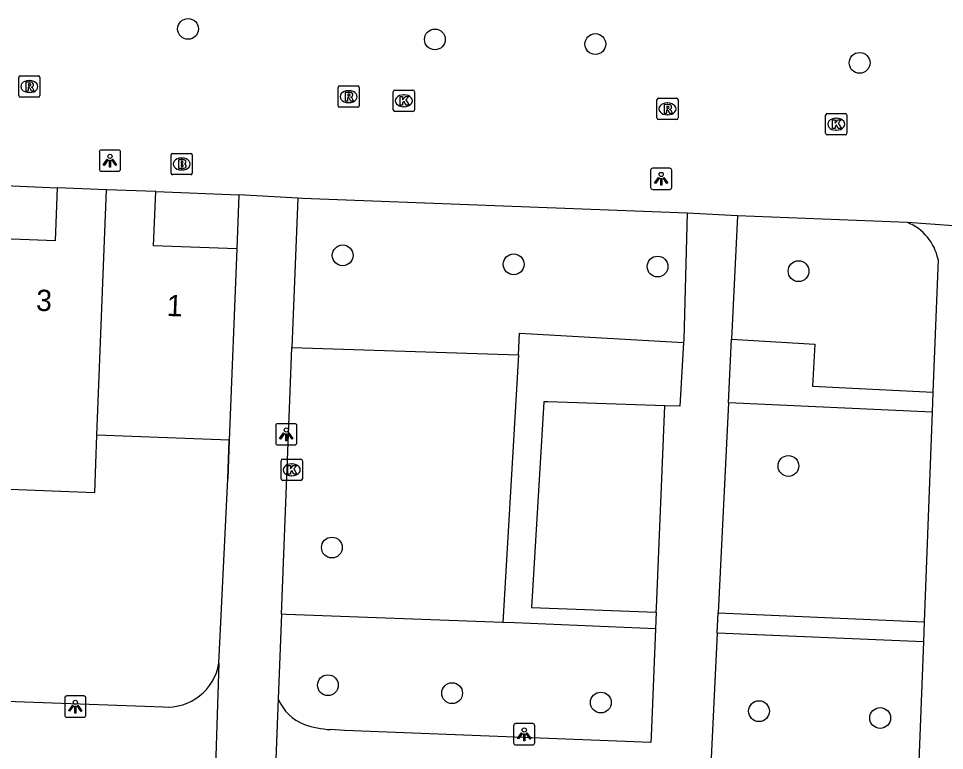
# Model space of a CAD drawing. Extents: x 160787 to 161428, y 386828 to 387483.
# Drawn here: x 161261.11 to 161304.65, y 387283.58 to 387318 of the extents above; entities that cross this region are included whole.
import ezdxf

# ---------------------------------------------------------------- set-up
doc = ezdxf.new("R2010")
doc.units = 0
for name, color, linetype in [('IMGEO_Boom', 7, 'Continuous'), ('IMGEO_Brandkraan', 7, 'Continuous'), ('IMGEO_Groenvoorziening', 7, 'Continuous'), ('IMGEO_Kolk', 7, 'Continuous'), ('IMGEO_Lichtpunt', 7, 'Continuous'), ('IMGEO_Muur', 7, 'Continuous'), ('IMGEO_Pand', 7, 'Continuous'), ('IMGEO_Pand_nummerreeks', 7, 'Continuous'), ('IMGEO_Rijbaan_lokaal_open', 7, 'Continuous'), ('IMGEO_Rioolput', 7, 'Continuous'), ('IMGEO_Voetpad_open', 7, 'Continuous')]:
    doc.layers.add(name, color=color, linetype=linetype)

msp = doc.modelspace()

# ---------------------------------------------------------------- linework, layer by layer
at = {"layer": 'IMGEO_Boom'}
for centre in [(161269.081, 387317.508), (161280.689, 387317.015), (161288.233, 387316.797), (161300.661, 387315.912), (161276.353, 387306.861), (161284.392, 387306.44), (161291.161, 387306.334), (161297.789, 387306.118), (161297.313, 387296.96), (161275.845, 387293.124), (161275.658, 387286.65), (161281.497, 387286.276), (161288.491, 387285.835), (161295.929, 387285.431), (161301.628, 387285.109)]:
    msp.add_circle(centre, 0.489, dxfattribs=at)
at = {"layer": 'IMGEO_Brandkraan'}
for p, q in [((161268.279, 387310.73), (161268.279, 387311.582)), ((161268.354, 387311.656), (161269.206, 387311.656)), ((161268.767, 387311.436), (161268.792, 387311.436)), ((161269.28, 387311.582), (161269.28, 387310.73)), ((161268.79, 387310.876), (161268.765, 387310.876)), ((161269.206, 387310.656), (161268.354, 387310.656))]:
    msp.add_line(p, q, dxfattribs=at)
for points in [[(161268.279, 387310.73), (161268.279, 387311.582)], [(161268.354, 387311.656), (161269.206, 387311.656)], [(161268.627, 387311.356), (161268.627, 387310.956), (161268.84, 387310.956)], [(161268.858, 387311.356), (161268.627, 387311.356)], [(161268.806, 387311.275), (161268.752, 387311.275), (161268.752, 387311.199)], [(161269.28, 387311.582), (161269.28, 387310.73)], [(161268.752, 387311.199), (161268.805, 387311.199)], [(161268.814, 387311.123), (161268.752, 387311.123), (161268.752, 387311.042)], [(161268.752, 387311.042), (161268.814, 387311.042)], [(161269.206, 387310.656), (161268.354, 387310.656)]]:
    msp.add_lwpolyline(points, dxfattribs=at)
for centre, radius, start, end in [((161268.356, 387311.58), 0.0765, 91.552, 178.448), ((161268.356, 387311.58), 0.0765, 91.552, 178.448), ((161268.807, 387311.237), 0.0379, 267.8285, 90.9355), ((161268.862, 387311.211), 0.145, 59.4692, 91.5367), ((161268.887, 387311.258), 0.0922, 285.5137, 58.1501), ((161269.204, 387311.58), 0.0765, 1.552, 88.448), ((161269.204, 387311.58), 0.0765, 1.552, 88.448), ((161268.815, 387311.082), 0.0404, 269.8759, 90.5077), ((161268.846, 387311.207), 0.251, 268.6676, 293.5347), ((161268.892, 387311.066), 0.105, 301.3115, 78.989), ((161268.356, 387310.732), 0.0765, 181.552, 268.448), ((161268.356, 387310.732), 0.0765, 181.552, 268.448), ((161269.204, 387310.732), 0.0765, 271.552, 358.448), ((161269.204, 387310.732), 0.0765, 271.552, 358.448)]:
    msp.add_arc(centre, radius, start, end, dxfattribs=at)
for centre, major_axis, ratio, start_param, end_param in [((161268.766, 387311.156), (-0.387, 0.002), 0.722429, 4.712389, 7.853982), ((161268.791, 387311.156), (-0.39, 0.002), 0.717154, 1.570796, 4.712389)]:
    msp.add_ellipse(centre, major_axis=major_axis, ratio=ratio, start_param=start_param, end_param=end_param, dxfattribs=at)
at = {"layer": 'IMGEO_Groenvoorziening'}
for points in [[(161273.964, 387302.526), (161284.613, 387302.181)], [(161283.889, 387289.598), (161273.705, 387289.978), (161273.479, 387289.987)]]:
    msp.add_lwpolyline(points, dxfattribs=at)
at = {"layer": 'IMGEO_Kolk'}
for p, q in [((161278.728, 387313.704), (161278.728, 387314.556)), ((161278.803, 387314.63), (161279.655, 387314.63)), ((161279.216, 387314.41), (161279.241, 387314.41)), ((161279.729, 387314.556), (161279.729, 387313.704)), ((161279.655, 387313.63), (161278.803, 387313.63)), ((161279.239, 387313.85), (161279.214, 387313.85)), ((161299.062, 387312.601), (161299.062, 387313.453)), ((161299.137, 387313.527), (161299.989, 387313.527)), ((161300.063, 387313.453), (161300.063, 387312.601)), ((161299.55, 387313.307), (161299.575, 387313.307)), ((161299.573, 387312.747), (161299.548, 387312.747)), ((161299.989, 387312.527), (161299.137, 387312.527)), ((161273.457, 387296.352), (161273.457, 387297.204)), ((161273.532, 387297.278), (161274.384, 387297.278)), ((161273.945, 387297.058), (161273.97, 387297.058)), ((161274.458, 387297.204), (161274.458, 387296.352)), ((161273.968, 387296.498), (161273.943, 387296.498)), ((161274.384, 387296.278), (161273.532, 387296.278))]:
    msp.add_line(p, q, dxfattribs=at)
for points in [[(161278.728, 387313.704), (161278.728, 387314.556)], [(161278.803, 387314.63), (161279.655, 387314.63)], [(161279.049, 387314.33), (161279.172, 387314.33), (161279.172, 387314.179), (161279.302, 387314.33), (161279.466, 387314.33), (161279.32, 387314.179), (161279.473, 387313.93), (161279.321, 387313.93), (161279.236, 387314.094), (161279.172, 387314.027), (161279.172, 387313.93), (161279.049, 387313.93), (161279.049, 387314.33)], [(161279.729, 387314.556), (161279.729, 387313.704)], [(161279.655, 387313.63), (161278.803, 387313.63)], [(161299.062, 387312.601), (161299.062, 387313.453)], [(161299.137, 387313.527), (161299.989, 387313.527)], [(161300.063, 387313.453), (161300.063, 387312.601)], [(161299.383, 387313.227), (161299.506, 387313.227), (161299.506, 387313.076), (161299.636, 387313.227), (161299.8, 387313.227), (161299.654, 387313.076), (161299.807, 387312.827), (161299.655, 387312.827), (161299.57, 387312.991), (161299.506, 387312.924), (161299.506, 387312.827), (161299.383, 387312.827), (161299.383, 387313.227)], [(161299.989, 387312.527), (161299.137, 387312.527)], [(161273.457, 387296.352), (161273.457, 387297.204)], [(161273.532, 387297.278), (161274.384, 387297.278)], [(161273.778, 387296.978), (161273.901, 387296.978), (161273.901, 387296.827), (161274.031, 387296.978), (161274.195, 387296.978), (161274.049, 387296.827), (161274.202, 387296.578), (161274.05, 387296.578), (161273.965, 387296.742), (161273.901, 387296.675), (161273.901, 387296.578), (161273.778, 387296.578), (161273.778, 387296.978)], [(161274.458, 387297.204), (161274.458, 387296.352)], [(161274.384, 387296.278), (161273.532, 387296.278)]]:
    msp.add_lwpolyline(points, dxfattribs=at)
for centre, start, end in [((161278.805, 387314.554), 91.552, 178.448), ((161278.805, 387314.554), 91.552, 178.448), ((161279.653, 387314.554), 1.552, 88.448), ((161279.653, 387314.554), 1.552, 88.448), ((161278.805, 387313.706), 181.552, 268.448), ((161278.805, 387313.706), 181.552, 268.448), ((161279.653, 387313.706), 271.552, 358.448), ((161279.653, 387313.706), 271.552, 358.448), ((161299.139, 387313.451), 91.552, 178.448), ((161299.139, 387313.451), 91.552, 178.448), ((161299.987, 387313.451), 1.552, 88.448), ((161299.987, 387313.451), 1.552, 88.448), ((161299.139, 387312.603), 181.552, 268.448), ((161299.139, 387312.603), 181.552, 268.448), ((161299.987, 387312.603), 271.552, 358.448), ((161299.987, 387312.603), 271.552, 358.448), ((161273.534, 387297.202), 91.552, 178.448), ((161273.534, 387297.202), 91.552, 178.448), ((161274.382, 387297.202), 1.552, 88.448), ((161274.382, 387297.202), 1.552, 88.448), ((161273.534, 387296.354), 181.552, 268.448), ((161273.534, 387296.354), 181.552, 268.448), ((161274.382, 387296.354), 271.552, 358.448), ((161274.382, 387296.354), 271.552, 358.448)]:
    msp.add_arc(centre, 0.0765, start, end, dxfattribs=at)
for centre, major_axis, ratio, start_param, end_param in [((161279.215, 387314.13), (-0.387, 0.002), 0.722429, 4.712389, 7.853982), ((161279.24, 387314.13), (-0.39, 0.002), 0.717154, 1.570796, 4.712389), ((161299.549, 387313.027), (-0.387, 0.002), 0.722429, 4.712389, 7.853982), ((161299.574, 387313.027), (-0.39, 0.002), 0.717154, 1.570796, 4.712389), ((161273.944, 387296.778), (-0.387, 0.002), 0.722429, 4.712389, 7.853982), ((161273.969, 387296.778), (-0.39, 0.002), 0.717154, 1.570796, 4.712389)]:
    msp.add_ellipse(centre, major_axis=major_axis, ratio=ratio, start_param=start_param, end_param=end_param, dxfattribs=at)
at = {"layer": 'IMGEO_Lichtpunt'}
for p, q in [((161264.909, 387311.72), (161264.909, 387310.913)), ((161264.909, 387311.72), (161264.909, 387310.913)), ((161265.811, 387311.815), (161265.003, 387311.815)), ((161265.811, 387311.815), (161265.003, 387311.815)), ((161265.905, 387310.913), (161265.905, 387311.72)), ((161265.905, 387310.913), (161265.905, 387311.72)), ((161265.003, 387310.819), (161265.811, 387310.819)), ((161265.003, 387310.819), (161265.811, 387310.819)), ((161290.831, 387310.866), (161290.831, 387310.059)), ((161290.831, 387310.866), (161290.831, 387310.059)), ((161291.733, 387310.961), (161290.925, 387310.961)), ((161291.733, 387310.961), (161290.925, 387310.961)), ((161291.827, 387310.059), (161291.827, 387310.866)), ((161291.827, 387310.059), (161291.827, 387310.866)), ((161290.925, 387309.965), (161291.733, 387309.965)), ((161290.925, 387309.965), (161291.733, 387309.965)), ((161273.201, 387298.853), (161273.201, 387298.046)), ((161273.201, 387298.853), (161273.201, 387298.046)), ((161274.103, 387298.948), (161273.295, 387298.948)), ((161274.103, 387298.948), (161273.295, 387298.948)), ((161274.197, 387298.046), (161274.197, 387298.853)), ((161274.197, 387298.046), (161274.197, 387298.853)), ((161273.295, 387297.952), (161274.103, 387297.952)), ((161273.295, 387297.952), (161274.103, 387297.952)), ((161263.281, 387286.049), (161263.281, 387285.242)), ((161263.281, 387286.049), (161263.281, 387285.242)), ((161264.183, 387286.144), (161263.375, 387286.144)), ((161264.183, 387286.144), (161263.375, 387286.144)), ((161264.277, 387285.242), (161264.277, 387286.049)), ((161264.277, 387285.242), (161264.277, 387286.049)), ((161263.375, 387285.148), (161264.183, 387285.148)), ((161263.375, 387285.148), (161264.183, 387285.148)), ((161284.391, 387284.748), (161284.391, 387283.941)), ((161284.391, 387284.748), (161284.391, 387283.941)), ((161285.293, 387284.843), (161284.485, 387284.843)), ((161285.293, 387284.843), (161284.485, 387284.843)), ((161285.387, 387283.941), (161285.387, 387284.748)), ((161285.387, 387283.941), (161285.387, 387284.748)), ((161284.485, 387283.847), (161285.293, 387283.847)), ((161284.485, 387283.847), (161285.293, 387283.847))]:
    msp.add_line(p, q, dxfattribs=at)
for points in [[(161265.283, 387311.384), (161265.322, 387311.356), (161265.134, 387311.094), (161265.096, 387311.121), (161265.283, 387311.384)], [(161265.385, 387311.336), (161265.432, 387311.336), (161265.432, 387311.014), (161265.385, 387311.014), (161265.385, 387311.336)], [(161265.495, 387311.356), (161265.533, 387311.383), (161265.72, 387311.121), (161265.681, 387311.093), (161265.495, 387311.356)], [(161291.205, 387310.53), (161291.244, 387310.502), (161291.056, 387310.24), (161291.018, 387310.267), (161291.205, 387310.53)], [(161291.307, 387310.482), (161291.354, 387310.482), (161291.354, 387310.16), (161291.307, 387310.16), (161291.307, 387310.482)], [(161291.417, 387310.502), (161291.455, 387310.529), (161291.642, 387310.267), (161291.603, 387310.239), (161291.417, 387310.502)], [(161273.575, 387298.517), (161273.614, 387298.489), (161273.426, 387298.227), (161273.388, 387298.254), (161273.575, 387298.517)], [(161273.677, 387298.469), (161273.724, 387298.469), (161273.724, 387298.147), (161273.677, 387298.147), (161273.677, 387298.469)], [(161273.787, 387298.489), (161273.825, 387298.516), (161274.012, 387298.254), (161273.973, 387298.226), (161273.787, 387298.489)], [(161263.655, 387285.713), (161263.694, 387285.685), (161263.506, 387285.423), (161263.468, 387285.45), (161263.655, 387285.713)], [(161263.757, 387285.665), (161263.804, 387285.665), (161263.804, 387285.343), (161263.757, 387285.343), (161263.757, 387285.665)], [(161263.867, 387285.685), (161263.905, 387285.712), (161264.092, 387285.45), (161264.053, 387285.422), (161263.867, 387285.685)], [(161284.765, 387284.412), (161284.804, 387284.384), (161284.616, 387284.122), (161284.578, 387284.149), (161284.765, 387284.412)], [(161284.867, 387284.364), (161284.914, 387284.364), (161284.914, 387284.042), (161284.867, 387284.042), (161284.867, 387284.364)], [(161284.977, 387284.384), (161285.015, 387284.411), (161285.202, 387284.149), (161285.163, 387284.121), (161284.977, 387284.384)]]:
    msp.add_lwpolyline(points, dxfattribs=at)
for centre in [(161265.408, 387311.518), (161291.33, 387310.664), (161273.7, 387298.651), (161263.78, 387285.847), (161284.89, 387284.546)]:
    msp.add_circle(centre, 0.0994, dxfattribs=at)
for centre, start, end in [((161265.003, 387311.72), 90, 180), ((161265.003, 387311.72), 90, 180), ((161265.811, 387311.72), 0, 90), ((161265.811, 387311.72), 0, 90), ((161265.003, 387310.913), 180, 270), ((161265.003, 387310.913), 180, 270), ((161265.811, 387310.913), 270, 0), ((161265.811, 387310.913), 270, 360), ((161290.925, 387310.866), 90, 180), ((161290.925, 387310.866), 90, 180), ((161291.733, 387310.866), 0, 90), ((161291.733, 387310.866), 0, 90), ((161290.925, 387310.059), 180, 270), ((161290.925, 387310.059), 180, 270), ((161291.733, 387310.059), 270, 0), ((161291.733, 387310.059), 270, 360), ((161273.295, 387298.853), 90, 180), ((161273.295, 387298.853), 90, 180), ((161274.103, 387298.853), 0, 90), ((161274.103, 387298.853), 0, 90), ((161273.295, 387298.046), 180, 270), ((161273.295, 387298.046), 180, 270), ((161274.103, 387298.046), 270, 0), ((161274.103, 387298.046), 270, 360), ((161263.375, 387286.049), 90, 180), ((161263.375, 387286.049), 90, 180), ((161264.183, 387286.049), 0, 90), ((161264.183, 387286.049), 0, 90), ((161263.375, 387285.242), 180, 270), ((161263.375, 387285.242), 180, 270), ((161264.183, 387285.242), 270, 0), ((161264.183, 387285.242), 270, 360), ((161284.485, 387284.748), 90, 180), ((161284.485, 387284.748), 90, 180), ((161285.293, 387284.748), 0, 90), ((161285.293, 387284.748), 0, 90), ((161284.485, 387283.941), 180, 270), ((161284.485, 387283.941), 180, 270), ((161285.293, 387283.941), 270, 0), ((161285.293, 387283.941), 270, 360)]:
    msp.add_arc(centre, 0.0946, start, end, dxfattribs=at)
at = {"layer": 'IMGEO_Muur'}
msp.add_lwpolyline([(161271.019, 387298.166), (161270.955, 387296.361)], dxfattribs=at)
at = {"layer": 'IMGEO_Pand'}
for points in [[(161262.928, 387310.038), (161262.831, 387307.54), (161259.138, 387307.685)], [(161265.248, 387309.947), (161262.928, 387310.038)], [(161264.797, 387298.409), (161265.248, 387309.947)], [(161267.563, 387309.857), (161265.248, 387309.947)], [(161271.371, 387307.164), (161267.463, 387307.317), (161267.563, 387309.857)], [(161271.371, 387307.164), (161271.019, 387298.166)], [(161258.784, 387298.645), (161258.678, 387295.946), (161264.691, 387295.71), (161264.797, 387298.409)], [(161271.019, 387298.166), (161264.797, 387298.409)]]:
    msp.add_lwpolyline(points, dxfattribs=at)
at = {"layer": 'IMGEO_Rijbaan_lokaal_open'}
for points in [[(161255.544, 387310.358), (161262.928, 387310.038)], [(161267.563, 387309.857), (161271.47, 387309.704)], [(161274.237, 387309.551), (161271.47, 387309.704)], [(161292.547, 387308.838), (161274.466, 387309.538), (161274.237, 387309.551)], [(161294.919, 387308.722), (161292.547, 387308.838)], [(161302.906, 387308.403), (161294.919, 387308.722)], [(161309.167, 387307.955), (161302.906, 387308.403)]]:
    msp.add_lwpolyline(points, dxfattribs=at)
at = {"layer": 'IMGEO_Rioolput'}
for p, q in [((161261.116, 387314.374), (161261.116, 387315.226)), ((161261.191, 387315.3), (161262.043, 387315.3)), ((161262.117, 387315.226), (161262.117, 387314.374)), ((161261.604, 387315.08), (161261.629, 387315.08)), ((161276.133, 387313.899), (161276.133, 387314.751)), ((161276.208, 387314.825), (161277.06, 387314.825)), ((161277.134, 387314.751), (161277.134, 387313.899)), ((161261.627, 387314.52), (161261.602, 387314.52)), ((161276.621, 387314.605), (161276.646, 387314.605)), ((161262.043, 387314.3), (161261.191, 387314.3)), ((161276.644, 387314.045), (161276.619, 387314.045)), ((161291.127, 387313.322), (161291.127, 387314.174)), ((161291.202, 387314.248), (161292.054, 387314.248)), ((161291.615, 387314.028), (161291.64, 387314.028)), ((161292.128, 387314.174), (161292.128, 387313.322)), ((161277.06, 387313.825), (161276.208, 387313.825)), ((161291.638, 387313.468), (161291.613, 387313.468)), ((161292.054, 387313.248), (161291.202, 387313.248))]:
    msp.add_line(p, q, dxfattribs=at)
for points in [[(161261.116, 387314.374), (161261.116, 387315.226)], [(161261.191, 387315.3), (161262.043, 387315.3)], [(161262.117, 387315.226), (161262.117, 387314.374)], [(161261.705, 387314.998), (161261.453, 387315), (161261.453, 387314.6)], [(161261.453, 387314.6), (161261.577, 387314.6), (161261.577, 387314.762), (161261.588, 387314.762)], [(161261.631, 387314.919), (161261.577, 387314.919), (161261.577, 387314.838)], [(161261.577, 387314.838), (161261.629, 387314.838)], [(161276.133, 387313.899), (161276.133, 387314.751)], [(161276.208, 387314.825), (161277.06, 387314.825)], [(161277.134, 387314.751), (161277.134, 387313.899)], [(161261.635, 387314.733), (161261.706, 387314.6), (161261.846, 387314.6), (161261.781, 387314.726)], [(161276.722, 387314.523), (161276.47, 387314.525), (161276.47, 387314.125)], [(161276.648, 387314.444), (161276.594, 387314.444), (161276.594, 387314.363)], [(161276.594, 387314.363), (161276.646, 387314.363)], [(161262.043, 387314.3), (161261.191, 387314.3)], [(161276.47, 387314.125), (161276.594, 387314.125), (161276.594, 387314.287), (161276.605, 387314.287)], [(161276.652, 387314.258), (161276.723, 387314.125), (161276.863, 387314.125), (161276.798, 387314.251)], [(161291.127, 387313.322), (161291.127, 387314.174)], [(161291.202, 387314.248), (161292.054, 387314.248)], [(161291.716, 387313.946), (161291.464, 387313.948), (161291.464, 387313.548)], [(161291.642, 387313.867), (161291.588, 387313.867), (161291.588, 387313.786)], [(161292.128, 387314.174), (161292.128, 387313.322)], [(161277.06, 387313.825), (161276.208, 387313.825)], [(161291.464, 387313.548), (161291.588, 387313.548), (161291.588, 387313.71), (161291.599, 387313.71)], [(161291.588, 387313.786), (161291.64, 387313.786)], [(161291.646, 387313.681), (161291.717, 387313.548), (161291.857, 387313.548), (161291.792, 387313.674)], [(161292.054, 387313.248), (161291.202, 387313.248)]]:
    msp.add_lwpolyline(points, dxfattribs=at)
for centre, radius, start, end in [((161261.193, 387315.224), 0.0765, 91.552, 178.448), ((161261.193, 387315.224), 0.0765, 91.552, 178.448), ((161262.041, 387315.224), 0.0765, 1.552, 88.448), ((161262.041, 387315.224), 0.0765, 1.552, 88.448), ((161261.587, 387314.709), 0.0533, 26.0293, 88.6989), ((161261.613, 387315.027), 0.19, 274.7715, 282.9687), ((161261.637, 387314.823), 0.0964, 77.0061, 93.1865), ((161261.651, 387314.88), 0.0378, 276.6634, 79.6772), ((161261.704, 387314.888), 0.109, 350.3612, 89.416), ((161261.702, 387314.888), 0.112, 277.5842, 350.9817), ((161261.686, 387314.673), 0.108, 29.5134, 73.7905), ((161276.21, 387314.749), 0.0765, 91.552, 178.448), ((161276.21, 387314.749), 0.0765, 91.552, 178.448), ((161277.058, 387314.749), 0.0765, 1.552, 88.448), ((161277.058, 387314.749), 0.0765, 1.552, 88.448), ((161261.193, 387314.376), 0.0765, 181.552, 268.448), ((161261.193, 387314.376), 0.0765, 181.552, 268.448), ((161262.041, 387314.376), 0.0765, 271.552, 358.448), ((161262.041, 387314.376), 0.0765, 271.552, 358.448), ((161276.63, 387314.552), 0.19, 274.7715, 282.9687), ((161276.654, 387314.348), 0.0964, 77.0061, 93.1865), ((161276.668, 387314.405), 0.0378, 276.6634, 79.6772), ((161276.721, 387314.413), 0.109, 350.3612, 89.416), ((161276.719, 387314.413), 0.112, 277.5842, 350.9817), ((161276.703, 387314.198), 0.108, 29.5134, 73.7905), ((161276.21, 387313.901), 0.0765, 181.552, 268.448), ((161276.21, 387313.901), 0.0765, 181.552, 268.448), ((161276.604, 387314.234), 0.0533, 26.0293, 88.6989), ((161277.058, 387313.901), 0.0765, 271.552, 358.448), ((161277.058, 387313.901), 0.0765, 271.552, 358.448), ((161291.204, 387314.172), 0.0765, 91.552, 178.448), ((161291.204, 387314.172), 0.0765, 91.552, 178.448), ((161291.648, 387313.771), 0.0964, 77.0061, 93.1865), ((161291.715, 387313.836), 0.109, 350.3612, 89.416), ((161292.052, 387314.172), 0.0765, 1.552, 88.448), ((161292.052, 387314.172), 0.0765, 1.552, 88.448), ((161291.598, 387313.657), 0.0533, 26.0293, 88.6989), ((161291.624, 387313.975), 0.19, 274.7715, 282.9687), ((161291.662, 387313.828), 0.0378, 276.6634, 79.6772), ((161291.713, 387313.836), 0.112, 277.5842, 350.9817), ((161291.697, 387313.621), 0.108, 29.5134, 73.7905), ((161291.204, 387313.324), 0.0765, 181.552, 268.448), ((161291.204, 387313.324), 0.0765, 181.552, 268.448), ((161292.052, 387313.324), 0.0765, 271.552, 358.448), ((161292.052, 387313.324), 0.0765, 271.552, 358.448)]:
    msp.add_arc(centre, radius, start, end, dxfattribs=at)
for centre, major_axis, ratio, start_param, end_param in [((161261.603, 387314.8), (-0.387, 0.002), 0.722429, 4.712389, 7.853982), ((161261.628, 387314.8), (-0.39, 0.002), 0.717154, 1.570796, 4.712389), ((161276.62, 387314.325), (-0.387, 0.002), 0.722429, 4.712389, 7.853982), ((161276.645, 387314.325), (-0.39, 0.002), 0.717154, 1.570796, 4.712389), ((161291.614, 387313.748), (-0.387, 0.002), 0.722429, 4.712389, 7.853982), ((161291.639, 387313.748), (-0.39, 0.002), 0.717154, 1.570796, 4.712389)]:
    msp.add_ellipse(centre, major_axis=major_axis, ratio=ratio, start_param=start_param, end_param=end_param, dxfattribs=at)
at = {"layer": 'IMGEO_Voetpad_open'}
for points in [[(161271.47, 387309.704), (161271.371, 387307.164)], [(161274.237, 387309.551), (161273.964, 387302.526)], [(161292.547, 387308.838), (161292.393, 387302.899), (161292.385, 387302.761)], [(161294.919, 387308.722), (161294.638, 387302.923)], [(161304.349, 387306.671), (161304.109, 387300.435)], [(161284.613, 387302.181), (161284.672, 387303.21), (161285.23, 387303.178), (161292.385, 387302.761)], [(161292.385, 387302.761), (161292.211, 387299.766), (161291.497, 387299.789)], [(161294.493, 387299.929), (161294.638, 387302.923)], [(161294.638, 387302.923), (161298.55, 387302.688), (161298.442, 387300.708), (161304.109, 387300.435)], [(161273.479, 387289.987), (161273.9, 387300.864), (161273.964, 387302.526)], [(161284.613, 387302.181), (161284.521, 387300.577), (161283.889, 387289.598)], [(161304.109, 387300.435), (161304.073, 387299.482)], [(161291.497, 387299.789), (161285.994, 387299.97), (161285.804, 387299.976), (161285.238, 387290.308), (161291.094, 387290.089)], [(161291.094, 387290.089), (161291.102, 387290.29), (161291.497, 387299.789)], [(161294.493, 387299.929), (161294.014, 387290.055)], [(161304.073, 387299.482), (161294.493, 387299.929)], [(161304.073, 387299.482), (161303.694, 387289.628)], [(161270.534, 387287.689), (161270.955, 387296.361), (161271.019, 387298.166)], [(161273.479, 387289.987), (161273.325, 387286.006)], [(161291.094, 387290.089), (161291.062, 387289.307)], [(161293.967, 387289.091), (161294.014, 387290.055)], [(161294.014, 387290.055), (161303.694, 387289.628)], [(161291.062, 387289.307), (161284.434, 387289.578), (161283.889, 387289.598)], [(161303.694, 387289.628), (161303.658, 387288.686)], [(161170.163, 387289.466), (161204.081, 387288.161), (161247.486, 387286.367), (161267.914, 387285.628)], [(161291.062, 387289.307), (161290.851, 387284.241), (161290.84, 387283.965), (161276.444, 387284.522), (161275.775, 387284.563)], [(161293.967, 387289.091), (161293.619, 387281.913)], [(161303.658, 387288.686), (161293.967, 387289.091)], [(161303.658, 387288.686), (161303.381, 387281.452)], [(161270.534, 387287.689), (161270.377, 387282.829)], [(161273.325, 387286.006), (161273.121, 387280.725)]]:
    msp.add_lwpolyline(points, dxfattribs=at)
for centre, radius, start, end in [((161302.035, 387306.211), 2.359, 11.2562, 68.3419), ((161268.099, 387288.088), 2.467, 265.689, 350.6911), ((161275.332, 387286.819), 2.165, 202.0493, 248.8922), ((161276.106, 387289.566), 5.014, 251.9424, 266.2135)]:
    msp.add_arc(centre, radius, start, end, dxfattribs=at)

# ---------------------------------------------------------------- texts
at = {"layer": 'IMGEO_Pand_nummerreeks'}
for s, rotation, p in [('3', 357.7082, (161261.918, 387304.26)), ('1', 357.7066, (161268.063, 387304.014))]:
    msp.add_text(s, height=1, rotation=rotation, dxfattribs=at).set_placement(p)

doc.saveas('drawing.dxf')
